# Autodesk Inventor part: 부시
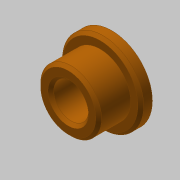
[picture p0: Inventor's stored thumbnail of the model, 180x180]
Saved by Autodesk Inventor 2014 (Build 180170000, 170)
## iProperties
Created: 2016-02
Part Number: 부시
Material: 강철, 연강
Document SubType Name: Modeling
Designer: test
Density: 1 g/cm^3
Appearance: Orange
Author: test
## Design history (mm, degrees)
sketch "스케치1"
  geometry: C1 r 14 at (0, 0); C2 r 10.5 at (0, 0); 1 further point
  constraints: 2 centre point, 2 coincident
  dimensions: "d0" = 28 diameter of C1; "d1" = 21 diameter of C2
extrude "돌출1" new body sketch "스케치1" distance "d2" = 4; taper "d3" = 0 deg
extrude "돌출2" join sketch "스케치1" distance "d4" = 11; taper "d5" = 0 deg
hole "구멍1" diameter "d8" = 12; stored, may be unused: countersink angle "d12" = 90 deg, drill point angle "d14" = 118 deg; dims "d6" = 10, "d7" = 10, "d9" = 6, "d10" = 4, "d11" = 2, "d13" = 8
chamfer "모따기1" distance "d15" = 1; stored, may be unused: second distance "d16" = 2, angle "d17" = 45 deg
chamfer "모따기2" distance "d18" = 1; stored, may be unused: second distance "d19" = 2, angle "d20" = 45 deg
node "솔리드1"
